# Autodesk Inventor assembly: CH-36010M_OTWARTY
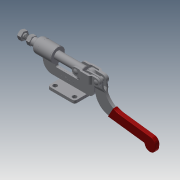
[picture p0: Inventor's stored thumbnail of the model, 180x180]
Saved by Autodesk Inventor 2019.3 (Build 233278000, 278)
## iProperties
Company: Î¢ÈíÖÐ¹ú
Created: 2012-09
Part Number: CH-36010M_OTWARTY
Material: Ogólny
Description: STEP AP203
Document SubType Name: Assembly
Designer: CADENGINEERING4
Sending System: SolidWorks 2010
Preprocessor: SwSTEP 2.0
Title: CH-36010M.STEP
Author: Î¢ÈíÓÃ»§
Revision Number: ÈÎºÎ
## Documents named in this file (14)
- D:\Vault_2016\Projekty\STRONA\Push-pull clamp\CH-36010M\CH-36010M_OTWARTY.iam
- D:\Vault_2016\Projekty\STRONA\Push-pull clamp\CH-36010M\CH-36010M-01 BASE.ipt
- D:\Vault_2016\Projekty\STRONA\Push-pull clamp\CH-36010M\CH-36010M-06.ipt
- D:\Vault_2016\Projekty\STRONA\Push-pull clamp\CH-36010M\CH-36010M-05 LEAD SET.ipt
- D:\Vault_2016\Projekty\STRONA\Push-pull clamp\CH-36010M\CH-36010M-04 CONNECTING-PLATE.ipt
- D:\Vault_2016\Projekty\STRONA\Push-pull clamp\CH-36010M\CH-36010M-08.ipt
- D:\Vault_2016\Projekty\STRONA\Push-pull clamp\CH-36010M\CH-36010M-09.ipt
- D:\Vault_2016\Projekty\STRONA\Push-pull clamp\CH-36010M\CH-36010M-10.ipt
- D:\Vault_2016\Projekty\STRONA\Push-pull clamp\CH-36010M\M10 Nut.ipt
- D:\Vault_2016\Projekty\STRONA\Push-pull clamp\CH-36010M\CH-36010M-02 CREST STALK.ipt
- D:\Vault_2016\Projekty\STRONA\Push-pull clamp\CH-36010M\CH-36010M-07.ipt
- D:\Vault_2016\Projekty\STRONA\Push-pull clamp\CH-36010M\CH-36010M-11.ipt
- D:\Vault_2016\Projekty\STRONA\Push-pull clamp\CH-36010M\CH-36010M-03 HANDLE.ipt
- D:\Vault_2016\Projekty\STRONA\Push-pull clamp\CH-36010M\CH-SA-105015 SPINDLE SUPPLIED.ipt
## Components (14 placed, 14 different names)
1. CH-36010M-01 BASE_1 — Zestawiające:5, Równoległe:1, Zestawiające:6, Zestawiające:14, Zestawiające:15
2. CH-36010M-06_2
3. CH-36010M-05 LEAD SET_3 — Zestawiające:14, Zestawiające:15, Zestawiające:16
4. CH-36010M-04 CONNECTING-PLATE_4 — Zestawiające:10, Zestawiające:11, Zestawiające:13, Zestawiające:17, Zestawiające:21, Zestawiające:23
5. CH-36010M-08_5 — Zestawiające:8, Równoległe:2, Zestawiające:11, Zestawiające:12, Zestawiające:20
6. CH-36010M-09_6 — Zestawiające:18, Zestawiające:19
7. CH-36010M-10_7 — Zestawiające:20, Zestawiające:21
8. M10 Nut_8 — Zestawiające:1, Zestawiające:2, Zestawiające:3
9. CH-36010M-02 CREST STALK_9 — Zestawiające:3, Zestawiające:4, Zestawiające:13, Zestawiające:16, Zestawiające:22
10. CH-36010M-07_10 — Zestawiające:5, Równoległe:1, Zestawiające:7, Zestawiające:18
11. CH-36010M-04 CONNECTING-PLATE_11 — Zestawiające:9, Zestawiające:12, Zestawiające:17
12. CH-36010M-11_12 — Zestawiające:22, Zestawiające:23
13. CH-36010M-03 HANDLE_13 — Zestawiające:6, Zestawiające:7, Zestawiające:8, Równoległe:2, Zestawiające:9, Zestawiające:10, Zestawiające:19
14. CH-SA-105015 SPINDLE SUPPLIED_14 — Zestawiające:1, Zestawiające:2, Zestawiające:4
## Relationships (25: Mate 23, Flush 2)
- Zestawiające:1 [Mate]: M10 Nut_8 ↔ CH-SA-105015 SPINDLE SUPPLIED_14
- Zestawiające:2 [Mate]: M10 Nut_8 ↔ CH-SA-105015 SPINDLE SUPPLIED_14
- Zestawiające:3 [Mate]: M10 Nut_8 ↔ CH-36010M-02 CREST STALK_9
- Zestawiające:4 [Mate]: CH-36010M-02 CREST STALK_9 ↔ CH-SA-105015 SPINDLE SUPPLIED_14
- Zestawiające:5 [Mate]: CH-36010M-01 BASE_1 ↔ CH-36010M-07_10
- Równoległe:1 [Flush]: CH-36010M-01 BASE_1 ↔ CH-36010M-07_10
- Zestawiające:6 [Mate]: CH-36010M-01 BASE_1 ↔ CH-36010M-03 HANDLE_13
- Zestawiające:7 [Mate]: CH-36010M-07_10 ↔ CH-36010M-03 HANDLE_13
- Zestawiające:8 [Mate]: CH-36010M-08_5 ↔ CH-36010M-03 HANDLE_13
- Równoległe:2 [Flush]: CH-36010M-08_5 ↔ CH-36010M-03 HANDLE_13
- Zestawiające:9 [Mate]: CH-36010M-04 CONNECTING-PLATE_11 ↔ CH-36010M-03 HANDLE_13
- Zestawiające:10 [Mate]: CH-36010M-04 CONNECTING-PLATE_4 ↔ CH-36010M-03 HANDLE_13
- Zestawiające:11 [Mate]: CH-36010M-04 CONNECTING-PLATE_4 ↔ CH-36010M-08_5
- Zestawiające:12 [Mate]: CH-36010M-08_5 ↔ CH-36010M-04 CONNECTING-PLATE_11
- Zestawiające:13 [Mate]: CH-36010M-04 CONNECTING-PLATE_4 ↔ CH-36010M-02 CREST STALK_9
- Zestawiające:14 [Mate]: CH-36010M-01 BASE_1 ↔ CH-36010M-05 LEAD SET_3
- Zestawiające:15 [Mate]: CH-36010M-01 BASE_1 ↔ CH-36010M-05 LEAD SET_3
- Zestawiające:16 [Mate]: CH-36010M-05 LEAD SET_3 ↔ CH-36010M-02 CREST STALK_9
- Zestawiające:17 [Mate]: CH-36010M-04 CONNECTING-PLATE_4 ↔ CH-36010M-04 CONNECTING-PLATE_11
- Zestawiające:18 [Mate]: CH-36010M-09_6 ↔ CH-36010M-07_10
- Zestawiające:19 [Mate]: CH-36010M-09_6 ↔ CH-36010M-03 HANDLE_13
- Zestawiające:20 [Mate]: CH-36010M-08_5 ↔ CH-36010M-10_7
- Zestawiające:21 [Mate]: CH-36010M-04 CONNECTING-PLATE_4 ↔ CH-36010M-10_7
- Zestawiające:22 [Mate]: CH-36010M-02 CREST STALK_9 ↔ CH-36010M-11_12
- Zestawiające:23 [Mate]: CH-36010M-04 CONNECTING-PLATE_4 ↔ CH-36010M-11_12
